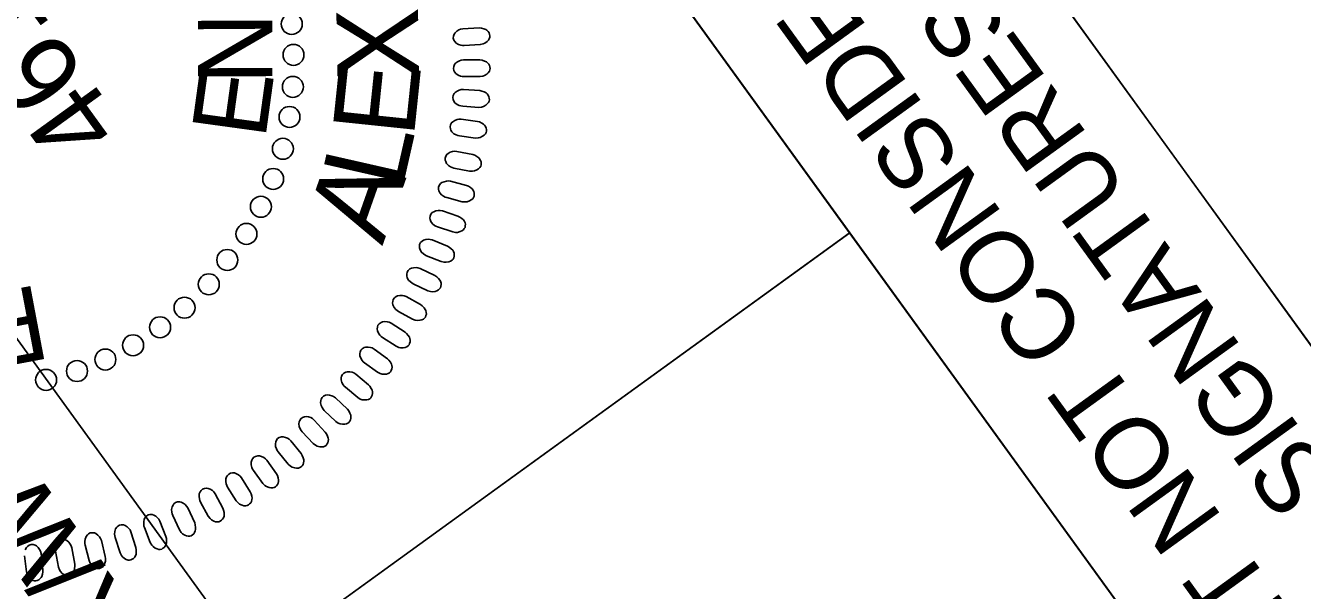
# Model space of a CAD drawing. Extents: x 474248 to 476123, y 501895 to 503900.
# Drawn here: x 474393.9 to 474491.3, y 503237.4 to 503280.5 of the extents above; entities that cross this region are included whole.
import ezdxf

# ---------------------------------------------------------------- set-up
doc = ezdxf.new("R2010")
doc.units = 0
for name, color, linetype in [('Scratch_Level_5', 7, 'Continuous'), ('Sheet Layout Plan Border', 7, 'Continuous'), ('Sheet PE Seal Cell', 7, 'Continuous'), ('Sheet Plan CELL', 7, 'Continuous'), ('Sheet Sticker Exception Certification CELL', 7, 'Continuous'), ('Sheet Sticker Incomplete CELL', 7, 'Continuous')]:
    doc.layers.add(name, color=color, linetype=linetype)

msp = doc.modelspace()

# ---------------------------------------------------------------- linework, layer by layer
at = {"layer": 'Scratch_Level_5'}
msp.add_lwpolyline([(474627.913, 502772.461), (474393.918, 503095.623), (474534.481, 503197.416), (474417.163, 503359.44), (475062.239, 503826.524), (475162.267, 503688.379), (475227.085, 503735.313), (475493.156, 503367.85)], close=True, dxfattribs=at)
at = {"layer": 'Sheet Layout Plan Border'}
msp.add_lwpolyline([(475148.793, 502314.888), (475799.674, 502786.065), (475874.954, 502840.561), (475397.529, 503499.918), (475353.895, 503468.323), (475265.228, 503590.778), (475283.66, 503604.124), (475199.913, 503719.785), (475161.571, 503692.033), (475161.571, 503692.033), (475161.571, 503692.033), (475161.571, 503692.033), (475161.571, 503692.033), (475063.524, 503827.461), (474417.163, 503359.44), (474534.481, 503197.416), (474393.908, 503095.616), (475024.421, 502224.855)], close=True, dxfattribs=at)
at = {"layer": 'Sheet PE Seal Cell'}
for points in [[(474427.354, 503278.965), (474428.579, 503279.04), (474428.796, 503279.09), (474428.932, 503279.151), (474429.095, 503279.273), (474429.198, 503279.377), (474429.27, 503279.493), (474429.305, 503279.6), (474429.317, 503279.714), (474429.291, 503279.824), (474429.254, 503279.942), (474429.187, 503280.043), (474429.081, 503280.141), (474428.998, 503280.196), (474428.845, 503280.254), (474428.662, 503280.303), (474428.501, 503280.316), (474427.247, 503280.246), (474427.079, 503280.214), (474426.942, 503280.16), (474426.788, 503280.061), (474426.656, 503279.941), (474426.582, 503279.839), (474426.531, 503279.679), (474426.521, 503279.528), (474426.57, 503279.381), (474426.626, 503279.28), (474426.733, 503279.159), (474426.909, 503279.05), (474427.093, 503278.994), (474427.224, 503278.972)], [(474427.325, 503276.596), (474428.552, 503276.594), (474428.771, 503276.631), (474428.911, 503276.683), (474429.081, 503276.794), (474429.191, 503276.892), (474429.271, 503277.004), (474429.311, 503277.108), (474429.331, 503277.22), (474429.311, 503277.332), (474429.281, 503277.452), (474429.222, 503277.557), (474429.122, 503277.661), (474429.043, 503277.722), (474428.893, 503277.789), (474428.714, 503277.849), (474428.555, 503277.872), (474427.298, 503277.882), (474427.128, 503277.86), (474426.988, 503277.815), (474426.829, 503277.726), (474426.688, 503277.614), (474426.609, 503277.517), (474426.548, 503277.36), (474426.528, 503277.21), (474426.568, 503277.061), (474426.618, 503276.956), (474426.717, 503276.829), (474426.886, 503276.71), (474427.066, 503276.641), (474427.196, 503276.611)], [(474427.235, 503274.332), (474428.459, 503274.252), (474428.68, 503274.276), (474428.823, 503274.318), (474429, 503274.419), (474429.115, 503274.51), (474429.202, 503274.616), (474429.249, 503274.718), (474429.277, 503274.829), (474429.263, 503274.941), (474429.241, 503275.063), (474429.189, 503275.171), (474429.095, 503275.282), (474429.02, 503275.348), (474428.875, 503275.424), (474428.7, 503275.495), (474428.542, 503275.528), (474427.288, 503275.617), (474427.118, 503275.606), (474426.975, 503275.569), (474426.811, 503275.491), (474426.664, 503275.388), (474426.578, 503275.296), (474426.508, 503275.143), (474426.479, 503274.995), (474426.509, 503274.844), (474426.552, 503274.735), (474426.643, 503274.602), (474426.804, 503274.473), (474426.98, 503274.393), (474427.107, 503274.355)], [(474426.986, 503272.066), (474428.203, 503271.91), (474428.426, 503271.919), (474428.571, 503271.953), (474428.753, 503272.042), (474428.875, 503272.125), (474428.968, 503272.226), (474429.02, 503272.324), (474429.055, 503272.433), (474429.049, 503272.547), (474429.034, 503272.67), (474428.989, 503272.781), (474428.903, 503272.897), (474428.832, 503272.967), (474428.692, 503273.053), (474428.521, 503273.135), (474428.366, 503273.178), (474427.12, 503273.345), (474426.95, 503273.344), (474426.805, 503273.317), (474426.636, 503273.249), (474426.483, 503273.156), (474426.392, 503273.069), (474426.312, 503272.921), (474426.273, 503272.775), (474426.294, 503272.622), (474426.33, 503272.512), (474426.412, 503272.373), (474426.566, 503272.233), (474426.735, 503272.143), (474426.86, 503272.097)], [(474426.564, 503269.617), (474427.768, 503269.385), (474427.99, 503269.38), (474428.138, 503269.405), (474428.326, 503269.483), (474428.451, 503269.558), (474428.551, 503269.653), (474428.61, 503269.748), (474428.651, 503269.854), (474428.652, 503269.968), (474428.646, 503270.092), (474428.607, 503270.205), (474428.528, 503270.327), (474428.462, 503270.4), (474428.327, 503270.495), (474428.163, 503270.588), (474428.01, 503270.64), (474426.778, 503270.885), (474426.607, 503270.896), (474426.461, 503270.877), (474426.288, 503270.82), (474426.129, 503270.737), (474426.033, 503270.656), (474425.944, 503270.513), (474425.897, 503270.37), (474425.907, 503270.216), (474425.937, 503270.104), (474426.01, 503269.96), (474426.154, 503269.811), (474426.318, 503269.71), (474426.439, 503269.657)], [(474426.015, 503267.356), (474427.203, 503267.048), (474427.424, 503267.03), (474427.573, 503267.045), (474427.765, 503267.111), (474427.896, 503267.178), (474428.001, 503267.266), (474428.066, 503267.357), (474428.113, 503267.461), (474428.122, 503267.574), (474428.123, 503267.698), (474428.091, 503267.814), (474428.021, 503267.94), (474427.958, 503268.018), (474427.83, 503268.121), (474427.672, 503268.224), (474427.523, 503268.286), (474426.308, 503268.608), (474426.139, 503268.629), (474425.992, 503268.62), (474425.816, 503268.573), (474425.652, 503268.5), (474425.55, 503268.426), (474425.453, 503268.289), (474425.396, 503268.149), (474425.398, 503267.995), (474425.42, 503267.881), (474425.484, 503267.732), (474425.618, 503267.574), (474425.775, 503267.464), (474425.893, 503267.403)], [(474425.314, 503265.116), (474426.481, 503264.734), (474426.7, 503264.702), (474426.849, 503264.707), (474427.045, 503264.762), (474427.18, 503264.82), (474427.29, 503264.902), (474427.361, 503264.988), (474427.415, 503265.089), (474427.431, 503265.202), (474427.439, 503265.325), (474427.415, 503265.443), (474427.353, 503265.573), (474427.295, 503265.655), (474427.174, 503265.766), (474427.023, 503265.878), (474426.878, 503265.95), (474425.686, 503266.347), (474425.517, 503266.378), (474425.371, 503266.379), (474425.191, 503266.343), (474425.024, 503266.28), (474424.918, 503266.213), (474424.812, 503266.082), (474424.747, 503265.946), (474424.738, 503265.792), (474424.753, 503265.677), (474424.808, 503265.525), (474424.932, 503265.359), (474425.082, 503265.239), (474425.196, 503265.17)], [(474424.463, 503262.924), (474425.603, 503262.47), (474425.82, 503262.423), (474425.969, 503262.42), (474426.169, 503262.462), (474426.306, 503262.511), (474426.422, 503262.586), (474426.498, 503262.668), (474426.558, 503262.765), (474426.58, 503262.877), (474426.597, 503262.999), (474426.58, 503263.118), (474426.526, 503263.252), (474426.474, 503263.337), (474426.36, 503263.455), (474426.215, 503263.577), (474426.076, 503263.657), (474424.911, 503264.129), (474424.745, 503264.171), (474424.598, 503264.18), (474424.418, 503264.157), (474424.246, 503264.104), (474424.136, 503264.043), (474424.022, 503263.919), (474423.949, 503263.788), (474423.93, 503263.634), (474423.938, 503263.519), (474423.984, 503263.363), (474424.097, 503263.19), (474424.239, 503263.061), (474424.348, 503262.985)], [(474423.461, 503260.77), (474424.57, 503260.246), (474424.784, 503260.186), (474424.932, 503260.173), (474425.134, 503260.202), (474425.275, 503260.243), (474425.394, 503260.31), (474425.475, 503260.388), (474425.541, 503260.481), (474425.571, 503260.59), (474425.595, 503260.712), (474425.586, 503260.831), (474425.54, 503260.969), (474425.494, 503261.057), (474425.387, 503261.182), (474425.251, 503261.313), (474425.116, 503261.402), (474423.983, 503261.946), (474423.82, 503261.998), (474423.675, 503262.016), (474423.493, 503262.004), (474423.319, 503261.962), (474423.204, 503261.908), (474423.084, 503261.792), (474423.001, 503261.665), (474422.974, 503261.513), (474422.974, 503261.397), (474423.01, 503261.24), (474423.112, 503261.059), (474423.246, 503260.921), (474423.35, 503260.839)], [(474422.334, 503258.662), (474423.408, 503258.069), (474423.618, 503257.996), (474423.766, 503257.973), (474423.969, 503257.99), (474424.112, 503258.022), (474424.236, 503258.082), (474424.321, 503258.154), (474424.393, 503258.242), (474424.429, 503258.35), (474424.461, 503258.47), (474424.459, 503258.59), (474424.422, 503258.73), (474424.382, 503258.821), (474424.283, 503258.952), (474424.155, 503259.091), (474424.026, 503259.188), (474422.93, 503259.802), (474422.77, 503259.864), (474422.627, 503259.893), (474422.444, 503259.891), (474422.267, 503259.861), (474422.15, 503259.814), (474422.022, 503259.705), (474421.932, 503259.584), (474421.895, 503259.434), (474421.888, 503259.318), (474421.914, 503259.159), (474422.005, 503258.973), (474422.129, 503258.826), (474422.228, 503258.738)], [(474421.113, 503256.667), (474422.147, 503256.007), (474422.353, 503255.921), (474422.498, 503255.89), (474422.702, 503255.893), (474422.847, 503255.916), (474422.974, 503255.968), (474423.063, 503256.035), (474423.141, 503256.119), (474423.184, 503256.223), (474423.223, 503256.341), (474423.229, 503256.461), (474423.201, 503256.603), (474423.166, 503256.696), (474423.076, 503256.834), (474422.957, 503256.98), (474422.834, 503257.085), (474421.779, 503257.767), (474421.624, 503257.839), (474421.482, 503257.876), (474421.299, 503257.886), (474421.121, 503257.867), (474421.001, 503257.828), (474420.867, 503257.728), (474420.769, 503257.612), (474420.723, 503257.465), (474420.709, 503257.35), (474420.724, 503257.189), (474420.804, 503256.997), (474420.918, 503256.844), (474421.012, 503256.749)], [(474419.746, 503254.74), (474420.737, 503254.018), (474420.936, 503253.918), (474421.079, 503253.878), (474421.283, 503253.869), (474421.429, 503253.883), (474421.559, 503253.926), (474421.653, 503253.987), (474421.735, 503254.066), (474421.785, 503254.168), (474421.831, 503254.283), (474421.845, 503254.402), (474421.825, 503254.545), (474421.797, 503254.641), (474421.715, 503254.783), (474421.605, 503254.938), (474421.49, 503255.05), (474420.479, 503255.797), (474420.329, 503255.878), (474420.19, 503255.924), (474420.008, 503255.946), (474419.829, 503255.938), (474419.707, 503255.906), (474419.567, 503255.814), (474419.462, 503255.705), (474419.407, 503255.561), (474419.385, 503255.447), (474419.391, 503255.286), (474419.457, 503255.09), (474419.562, 503254.929), (474419.65, 503254.829)], [(474418.279, 503252.872), (474419.223, 503252.087), (474419.415, 503251.976), (474419.556, 503251.927), (474419.758, 503251.905), (474419.905, 503251.91), (474420.038, 503251.945), (474420.135, 503252), (474420.222, 503252.074), (474420.278, 503252.172), (474420.332, 503252.283), (474420.353, 503252.402), (474420.343, 503252.547), (474420.32, 503252.644), (474420.248, 503252.791), (474420.148, 503252.952), (474420.039, 503253.071), (474419.078, 503253.88), (474418.933, 503253.971), (474418.797, 503254.025), (474418.617, 503254.058), (474418.438, 503254.061), (474418.315, 503254.037), (474418.168, 503253.955), (474418.057, 503253.852), (474417.992, 503253.712), (474417.964, 503253.6), (474417.959, 503253.438), (474418.013, 503253.238), (474418.108, 503253.071), (474418.189, 503252.966)], [(474416.664, 503251.11), (474417.557, 503250.269), (474417.742, 503250.145), (474417.879, 503250.087), (474418.08, 503250.053), (474418.226, 503250.048), (474418.361, 503250.075), (474418.462, 503250.124), (474418.553, 503250.192), (474418.615, 503250.287), (474418.675, 503250.395), (474418.704, 503250.512), (474418.703, 503250.656), (474418.686, 503250.754), (474418.624, 503250.906), (474418.534, 503251.073), (474418.434, 503251.199), (474417.524, 503252.066), (474417.385, 503252.166), (474417.253, 503252.229), (474417.076, 503252.273), (474416.897, 503252.288), (474416.772, 503252.272), (474416.621, 503252.199), (474416.504, 503252.103), (474416.43, 503251.967), (474416.395, 503251.857), (474416.38, 503251.696), (474416.422, 503251.493), (474416.506, 503251.32), (474416.58, 503251.21)], [(474414.976, 503249.476), (474415.814, 503248.58), (474415.991, 503248.446), (474416.124, 503248.379), (474416.322, 503248.332), (474416.468, 503248.318), (474416.605, 503248.337), (474416.708, 503248.379), (474416.804, 503248.441), (474416.872, 503248.532), (474416.939, 503248.636), (474416.975, 503248.751), (474416.983, 503248.896), (474416.972, 503248.995), (474416.919, 503249.15), (474416.84, 503249.322), (474416.747, 503249.454), (474415.895, 503250.377), (474415.763, 503250.485), (474415.634, 503250.556), (474415.46, 503250.612), (474415.283, 503250.637), (474415.157, 503250.629), (474415.001, 503250.565), (474414.879, 503250.478), (474414.797, 503250.347), (474414.754, 503250.238), (474414.729, 503250.079), (474414.758, 503249.874), (474414.832, 503249.697), (474414.899, 503249.581)], [(474413.144, 503247.947), (474413.924, 503247), (474414.092, 503246.854), (474414.221, 503246.779), (474414.416, 503246.72), (474414.561, 503246.697), (474414.698, 503246.707), (474414.804, 503246.743), (474414.903, 503246.799), (474414.976, 503246.885), (474415.05, 503246.985), (474415.093, 503247.097), (474415.11, 503247.241), (474415.106, 503247.34), (474415.062, 503247.498), (474414.994, 503247.675), (474414.911, 503247.812), (474414.117, 503248.787), (474413.991, 503248.904), (474413.869, 503248.982), (474413.697, 503249.049), (474413.522, 503249.085), (474413.397, 503249.086), (474413.237, 503249.032), (474413.109, 503248.952), (474413.019, 503248.826), (474412.97, 503248.721), (474412.936, 503248.563), (474412.951, 503248.357), (474413.013, 503248.175), (474413.073, 503248.056)], [(474411.265, 503246.522), (474411.984, 503245.528), (474412.143, 503245.372), (474412.267, 503245.289), (474412.457, 503245.218), (474412.6, 503245.186), (474412.738, 503245.187), (474412.846, 503245.216), (474412.949, 503245.266), (474413.027, 503245.347), (474413.107, 503245.442), (474413.157, 503245.551), (474413.183, 503245.694), (474413.185, 503245.793), (474413.152, 503245.954), (474413.095, 503246.135), (474413.02, 503246.277), (474412.289, 503247.3), (474412.172, 503247.424), (474412.053, 503247.511), (474411.887, 503247.587), (474411.714, 503247.635), (474411.589, 503247.642), (474411.427, 503247.599), (474411.294, 503247.527), (474411.196, 503247.407), (474411.141, 503247.305), (474411.095, 503247.15), (474411.098, 503246.943), (474411.149, 503246.758), (474411.201, 503246.635)], [(474409.284, 503245.249), (474409.939, 503244.212), (474410.089, 503244.046), (474410.207, 503243.955), (474410.392, 503243.872), (474410.534, 503243.831), (474410.671, 503243.824), (474410.781, 503243.846), (474410.886, 503243.889), (474410.97, 503243.966), (474411.055, 503244.055), (474411.112, 503244.161), (474411.147, 503244.301), (474411.155, 503244.401), (474411.132, 503244.563), (474411.087, 503244.747), (474411.02, 503244.894), (474410.355, 503245.96), (474410.246, 503246.092), (474410.133, 503246.185), (474409.972, 503246.272), (474409.803, 503246.331), (474409.678, 503246.347), (474409.514, 503246.313), (474409.376, 503246.25), (474409.272, 503246.137), (474409.209, 503246.038), (474409.155, 503245.886), (474409.145, 503245.679), (474409.184, 503245.491), (474409.228, 503245.366)], [(474407.218, 503244.106), (474407.807, 503243.03), (474407.945, 503242.855), (474408.057, 503242.757), (474408.237, 503242.663), (474408.375, 503242.613), (474408.512, 503242.597), (474408.623, 503242.612), (474408.731, 503242.649), (474408.819, 503242.72), (474408.91, 503242.804), (474408.973, 503242.906), (474409.017, 503243.044), (474409.031, 503243.143), (474409.019, 503243.306), (474408.985, 503243.492), (474408.928, 503243.643), (474408.331, 503244.749), (474408.23, 503244.887), (474408.124, 503244.988), (474407.969, 503245.085), (474407.803, 503245.153), (474407.679, 503245.176), (474407.513, 503245.154), (474407.372, 503245.1), (474407.261, 503244.993), (474407.192, 503244.899), (474407.129, 503244.751), (474407.106, 503244.544), (474407.133, 503244.354), (474407.169, 503244.227)], [(474405.097, 503243.089), (474405.617, 503241.978), (474405.744, 503241.795), (474405.85, 503241.69), (474406.024, 503241.585), (474406.158, 503241.526), (474406.294, 503241.502), (474406.405, 503241.51), (474406.515, 503241.539), (474406.608, 503241.605), (474406.704, 503241.683), (474406.773, 503241.781), (474406.825, 503241.916), (474406.846, 503242.014), (474406.844, 503242.178), (474406.822, 503242.366), (474406.775, 503242.52), (474406.249, 503243.662), (474406.156, 503243.805), (474406.056, 503243.913), (474405.908, 503244.019), (474405.747, 503244.098), (474405.625, 503244.129), (474405.457, 503244.117), (474405.313, 503244.072), (474405.195, 503243.972), (474405.121, 503243.882), (474405.048, 503243.738), (474405.012, 503243.534), (474405.027, 503243.343), (474405.055, 503243.212)], [(474402.937, 503242.157), (474403.387, 503241.015), (474403.502, 503240.825), (474403.601, 503240.714), (474403.768, 503240.598), (474403.899, 503240.531), (474404.032, 503240.497), (474404.144, 503240.499), (474404.256, 503240.522), (474404.353, 503240.581), (474404.454, 503240.653), (474404.529, 503240.747), (474404.589, 503240.878), (474404.616, 503240.974), (474404.624, 503241.138), (474404.613, 503241.327), (474404.576, 503241.484), (474404.123, 503242.656), (474404.04, 503242.805), (474403.947, 503242.919), (474403.805, 503243.034), (474403.65, 503243.123), (474403.53, 503243.162), (474403.362, 503243.16), (474403.216, 503243.124), (474403.091, 503243.032), (474403.012, 503242.947), (474402.93, 503242.808), (474402.881, 503242.607), (474402.884, 503242.415), (474402.904, 503242.283)], [(474398.41, 503240.83), (474398.713, 503239.642), (474398.804, 503239.439), (474398.888, 503239.316), (474399.039, 503239.179), (474399.16, 503239.097), (474399.289, 503239.048), (474399.4, 503239.035), (474399.514, 503239.043), (474399.617, 503239.09), (474399.726, 503239.149), (474399.812, 503239.232), (474399.889, 503239.354), (474399.928, 503239.447), (474399.956, 503239.608), (474399.969, 503239.797), (474399.952, 503239.957), (474399.649, 503241.176), (474399.585, 503241.335), (474399.507, 503241.46), (474399.381, 503241.592), (474399.238, 503241.7), (474399.124, 503241.753), (474398.957, 503241.773), (474398.808, 503241.755), (474398.673, 503241.68), (474398.583, 503241.605), (474398.485, 503241.477), (474398.411, 503241.284), (474398.39, 503241.093), (474398.393, 503240.959)], [(474400.697, 503241.405), (474401.074, 503240.238), (474401.177, 503240.04), (474401.27, 503239.923), (474401.428, 503239.796), (474401.555, 503239.722), (474401.686, 503239.68), (474401.797, 503239.674), (474401.91, 503239.69), (474402.011, 503239.744), (474402.116, 503239.809), (474402.197, 503239.897), (474402.266, 503240.025), (474402.298, 503240.119), (474402.317, 503240.282), (474402.318, 503240.471), (474402.29, 503240.63), (474401.912, 503241.829), (474401.838, 503241.983), (474401.752, 503242.102), (474401.618, 503242.226), (474401.469, 503242.324), (474401.352, 503242.371), (474401.184, 503242.38), (474401.036, 503242.353), (474400.905, 503242.268), (474400.822, 503242.189), (474400.73, 503242.055), (474400.669, 503241.857), (474400.66, 503241.665), (474400.672, 503241.533)], [(474396.143, 503240.349), (474396.371, 503239.143), (474396.448, 503238.935), (474396.525, 503238.807), (474396.667, 503238.661), (474396.783, 503238.571), (474396.908, 503238.514), (474397.018, 503238.494), (474397.132, 503238.495), (474397.238, 503238.536), (474397.351, 503238.588), (474397.442, 503238.665), (474397.526, 503238.783), (474397.57, 503238.872), (474397.609, 503239.032), (474397.634, 503239.22), (474397.627, 503239.38), (474397.401, 503240.617), (474397.347, 503240.779), (474397.277, 503240.908), (474397.16, 503241.048), (474397.024, 503241.164), (474396.914, 503241.225), (474396.748, 503241.255), (474396.597, 503241.246), (474396.458, 503241.179), (474396.364, 503241.111), (474396.258, 503240.99), (474396.172, 503240.801), (474396.139, 503240.612), (474396.134, 503240.479)]]:
    msp.add_lwpolyline(points, close=True, dxfattribs=at)
msp.add_lwpolyline([(474393.773, 503240.002), (474393.924, 503238.784), (474393.988, 503238.571), (474394.057, 503238.439), (474394.189, 503238.284), (474394.3, 503238.187), (474394.42, 503238.122), (474394.529, 503238.096), (474394.643, 503238.089), (474394.752, 503238.123), (474394.867, 503238.168), (474394.963, 503238.24), (474395.055, 503238.352), (474395.104, 503238.438), (474395.153, 503238.595), (474395.19, 503238.78), (474395.192, 503238.942), (474395.045, 503240.189), (474395.002, 503240.355), (474394.94, 503240.488), (474394.831, 503240.635), (474394.703, 503240.76), (474394.596, 503240.827), (474394.433, 503240.867), (474394.282, 503240.868), (474394.139, 503240.81), (474394.042, 503240.749), (474393.927, 503240.634), (474393.83, 503240.451)], dxfattribs=at)
for centre in [(474414.186, 503280.62), (474414.32, 503278.26), (474414.27, 503275.816), (474414.014, 503273.518), (474413.51, 503271.089), (474412.768, 503268.784), (474411.831, 503266.662), (474410.727, 503264.585), (474409.266, 503262.595), (474407.855, 503260.739), (474406, 503258.954), (474404.133, 503257.456), (474402.072, 503256.083), (474399.958, 503254.996), (474397.791, 503254.116), (474395.429, 503253.44)]:
    msp.add_circle(centre, 0.801, dxfattribs=at)
at = {"layer": 'Sheet Plan CELL'}
msp.add_line((474365.666, 503198.69), (474456.749, 503264.656), dxfattribs=at)
for points in [[(476006.781, 502658.499), (475156.352, 502042.692), (474393.908, 503095.616), (474515.447, 503183.634), (474398.139, 503345.665), (475127.058, 503873.458)], [(474365.666, 503198.69), (474307.015, 503279.669), (474398.139, 503345.665), (474456.797, 503264.676)], [(474424.343, 503117.653), (474365.666, 503198.69), (474456.797, 503264.676), (474515.447, 503183.634)]]:
    msp.add_lwpolyline(points, close=True, dxfattribs=at)
at = {"layer": 'Sheet Sticker Exception Certification CELL'}
for p, q in [((474417.163, 503359.44), (474534.481, 503197.416)), ((474417.163, 503359.44), (474534.481, 503197.416)), ((474515.447, 503183.634), (474398.129, 503345.658)), ((474515.447, 503183.634), (474398.129, 503345.658))]:
    msp.add_line(p, q, dxfattribs=at)
at = {"layer": 'Sheet Sticker Incomplete CELL'}
msp.add_lwpolyline([(474454.332, 503172.147), (474435.298, 503158.364), (474349.086, 503277.429), (474368.12, 503291.211)], close=True, dxfattribs=at)

# ---------------------------------------------------------------- texts
at = {"layer": 'Sheet PE Seal Cell'}
for s, height, rotation, p in [('46155', 6.2363, 125.8852, (474401.372, 503272.887)), ('X', 6.236, 90.89828, (474423.91, 503276.364)), ('N', 5.669, 90.10922, (474412.709, 503276.011)), ('E', 5.669, 82.16943, (474412.154, 503271.738)), ('E', 6.236, 84.05262, (474423.497, 503271.866)), ('L', 6.236, 77.20696, (474422.592, 503267.861)), ('A', 6.236, 70.58729, (474421.101, 503263.645)), ('P', 5.669, 190.71125, (474394.838, 503260.72))]:
    msp.add_text(s, height=height, rotation=rotation, dxfattribs=at).set_placement(p)
at = {"layer": 'Sheet Sticker Exception Certification CELL'}
for s, p in [('UNLESS ALL SIGNATURES COMPLETED', (474521.57, 503207.822)), ('UNLESS ALL SIGNATURES COMPLETED', (474521.57, 503207.822)), ('DOCUMENT NOT CONSIDERED FINAL', (474511.468, 503206.768)), ('DOCUMENT NOT CONSIDERED FINAL', (474511.468, 503206.768))]:
    msp.add_text(s, height=5.5, rotation=125.90742, dxfattribs=at).set_placement(p)
at = {"layer": 'Sheet Sticker Incomplete CELL'}
for s, height, p in [('INCOMPLETE PLANS', 11.52, (474439.607, 503172.534)), ('DO NOT USE FOR R/W ACQUISITION', 5.76, (474443.33, 503179.242))]:
    msp.add_text(s, height=height, rotation=125.90742, dxfattribs=at).set_placement(p)

doc.saveas('drawing.dxf')
